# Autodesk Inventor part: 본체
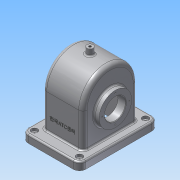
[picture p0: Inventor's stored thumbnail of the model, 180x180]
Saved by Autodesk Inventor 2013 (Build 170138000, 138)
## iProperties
Created: 2016-10
Part Number: 본체
Material: 알루미늄 6061
Document SubType Name: Modeling
Designer: Administrator
Density: 2.71 g/cm^3
Mass: 1073.23 g
Surface Area: 1162.36 cm^2
Volume: 396.027 cm^3
Author: Administrator
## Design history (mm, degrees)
sketch "스케치1"
  geometry: L1 (-43, 75)-(43, 75); L2 (55, 63)-(55, -63); L3 (43, -75)-(-43, -75); L4 (-55, -63)-(-55, 63); A1 r 12 centre (-43, 63) between (-43, 75) and (-55, 63); A2 r 12 centre (43, 63) between (55, 63) and (43, 75); A3 r 12 centre (-43, -63) between (-55, -63) and (-43, -75); A4 r 12 centre (43, -63) between (43, -75) and (55, -63); 6 further points
  constraints: 8 end point, 8 point on circle, 8 tangent, 6 point on line, 4 centre point, 3 equal radius, 2 midpoint, 2 parallel, 1 horizontal, 1 horizontal alignment, 1 perpendicular, 1 vertical alignment
  dimensions: "d0" = 110 distance of point (-55, 75) point (55, 75); "d2" = 150 distance of point (55, 75) point (55, -75); "d3" = 12 radius of A1
extrude "돌출1" new body sketch "스케치1" distance "d4" = 15; taper "d5" = 0 deg
sketch "스케치2"
  geometry: L1 (63, 15)-(-63, 15) reference; L2 (-63, 15)-(-75, 15) reference; L3 (75, 15)-(63, 15) reference; L4 (-63, 0)-(-75, 0) reference; L5 (-52, 15)-(-52, 80); L6 (52, 80)-(52, 15); A1 r 52 centre (0, 80) between (52, 80) and (-52, 80); 1 further point
  constraints: 4 end point, 2 perpendicular, 2 point on circle, 2 point on line, 2 tangent, 1 centre point, 1 vertical alignment
  dimensions: "d9" = 52 radius of A1; "d11" = 80 distance from line of L4 L5.end
extrude "돌출2" join sketch "스케치2" distance "d12" = 38.5; taper "d13" = 0 deg
node "작업 평면1"
extrude "돌출3" join sketch "스케치2" distance "d15" = 38.5; taper "d16" = 0 deg
node "작업 평면2"
sketch "스케치3"
  geometry: C1 r 6 at (0, 0); 1 further point
  constraints: 1 centre point, 1 coincident
  dimensions: "d18" = 12 diameter of C1
extrude "돌출4" join sketch "스케치3" distance "d20" = 38; taper "d21" = 0 deg
node "작업 평면3"
node "작업 평면4"
node "작업 평면5"
sketch "스케치6"
  geometry: L1 (-63, 0)-(63, 0) reference; C1 r 37.5 at (0, 65); 2 further points
  constraints: 1 centre point, 1 midpoint, 1 vertical alignment
  dimensions: "d33" = 75 diameter of C1; "d35" = 65 distance from line of L1 C1.centre
extrude "돌출6" join sketch "스케치6" distance "d36" = 5; taper "d37" = 0 deg
node "작업 평면7"
  node "작업 평면6"
node "작업 평면8"
sketch "스케치9"
  geometry: L1 (-63, 0)-(63, 0) reference; C1 r 31 at (0, 65); 2 further points
  constraints: 1 centre point, 1 midpoint, 1 vertical alignment
  dimensions: "d55" = 65 distance from line of L1 C1.centre; "d56" = 62 diameter of C1
extrude "돌출7" join sketch "스케치9" distance "d57" = 10; taper "d58" = 0 deg
sketch "스케치10"
  geometry: L1 (52, 80)-(52, 15) reference; L2 (-52, 15)-(-52, 80) reference; L3 (63, 0)-(-63, 0) reference; L4 (-46, 0)-(-46, 80); L5 (46, 80)-(46, 0); A1 r 52 centre (0, 80) between (52, 80) and (-52, 80) reference; A2 r 46 centre (0, 80) between (46, 80) and (-46, 80); 1 further point
  constraints: 4 end point, 2 point on circle, 2 point on line, 1 centre point
  dimensions: "d59" = 6 radial gap between concentric circles of A1 A2; "d60" = 6 distance between parallel lines of L2 L4; "d61" = 6 distance between parallel lines of L1 L5
extrude "돌출8" cut sketch "스케치10" stored distance "d62" = 67; taper "d63" = 0 deg
node "작업 평면10"
  node "작업 평면9"
sketch "스케치11"
  geometry: L1 (-43.5, 65)-(-19.5, 65); L2 (-19.5, 65)-(-19.5, 93); L3 (-43.5, 102.5)-(-43.5, 27.5) reference; L4 (-38.5, 132)-(-38.5, 80) reference; L5 (-19.5, 93)-(-33.5, 104.747); L6 (-33.5, 126)-(-33.5, 80) reference; L7 (-33.5, 104.747)-(-33.5, 85); L8 (-43.5, 85)-(-33.5, 85); L9 (-43.5, 85)-(-43.5, 65); 1 further point
  constraints: 12 end point, 3 point on line, 2 perpendicular, 1 collinear, 1 midpoint
  dimensions: "d66" = 65 distance from line of point (0, 0) L1; "d69" = 24 distance between parallel lines of L2 L3; "d73" = 56 diameter of L2.end L1; "d74" = 50 deg angle of L2 L5; "d75" = 40 diameter of L8 L1
revolve "회전1" sketch "스케치11" stored, may be unused: angle "d76" = 90 deg
hole "구멍1" diameter "d79" = 40; stored, may be unused: countersink angle "d83" = 90 deg, drill point angle "d85" = 0 deg; dims "d77" = 10, "d78" = 10, "d80" = 6, "d81" = 4, "d82" = 2, "d84" = 15
node "작업 평면11"
sketch "스케치12"
  geometry: L1 (43, 0)-(-43, 0) reference; L2 (-38.5, 80)-(-38.5, 15) reference; 3 further points
  constraints: 1 coincident, 1 other
  dimensions: "d87" = 40 distance from line of point (0, 40) L1; "d88" = 38.5 distance from line of point (0, 40) L2
feature "엠보싱1" sketch "스케치12" dims "d89" = 0.5, "d90" = 0
hole "구멍2" diameter "d93" = 5; stored, may be unused: countersink angle "d97" = 90 deg, drill point angle "d99" = 0 deg; dims "d91" = 10, "d92" = 10, "d94" = 6, "d95" = 12, "d96" = 5, "d98" = 15
hole "구멍3" diameter "d102" = 5; stored, may be unused: countersink angle "d106" = 90 deg, drill point angle "d108" = 0 deg; dims "d100" = 10, "d101" = 10, "d103" = 6, "d104" = 12, "d105" = 5, "d107" = 15
hole "구멍4" diameter "d111" = 5; stored, may be unused: countersink angle "d115" = 90 deg, drill point angle "d117" = 0 deg; dims "d109" = 10, "d110" = 10, "d112" = 6, "d113" = 12, "d114" = 5, "d116" = 15
hole "구멍5" diameter "d120" = 5; stored, may be unused: countersink angle "d124" = 90 deg, drill point angle "d126" = 0 deg; dims "d118" = 10, "d119" = 10, "d121" = 6, "d122" = 12, "d123" = 5, "d125" = 15
hole "구멍6" diameter "d129" = 4.459; stored, may be unused: countersink angle "d133" = 90 deg, drill point angle "d135" = 118 deg; dims "d127" = 10, "d128" = 10, "d130" = 6, "d131" = 12, "d132" = 5, "d134" = 15
sketch "스케치13" dims "d136" = 58
  geometry: C1 r 20 at (0, 0) reference; 3 further points
  constraints: 2 vertical alignment, 1 coincident, 2 other
hole "구멍7" sketch "스케치13" at (0, 29) diameter "d138" = 2.459; stored, may be unused: countersink angle "d142" = 90 deg, drill point angle "d144" = 118 deg; dims "d139" = 6, "d140" = 12, "d141" = 5, "d143" = 8
sketch "스케치14" dims "d148" = 52
  geometry: C1 r 20 at (0, 0) reference; 3 further points
  constraints: 2 horizontal alignment, 1 coincident, 2 other
hole "구멍8" sketch "스케치14" at (-26, 0) diameter "d150" = 2.459; stored, may be unused: countersink angle "d154" = 90 deg, drill point angle "d156" = 118 deg; dims "d151" = 6, "d152" = 12, "d153" = 5, "d155" = 8
chamfer "모따기1" distance "d160" = 1; stored, may be unused: second distance "d161" = 2, angle "d162" = 45 deg
fillet "모깎기1" dims "d163" = 8
fillet "모깎기2" dims "d164" = 8
fillet "모깎기3" dims "d165" = 3
fillet "모깎기4" dims "d166" = 3
fillet "모깎기5" dims "d167" = 3
node "솔리드1"
pattern_circular "원형 패턴1" dims angle "d146" = 360 deg
pattern_circular "원형 패턴2" dims angle "d158" = 360 deg
other parameters: "d14" = 144, "d17" = 144, "d22" = -38.5, "d28" = 38.5, "d32" = -38.5, "d42" = 56, "d54" = 38.5
